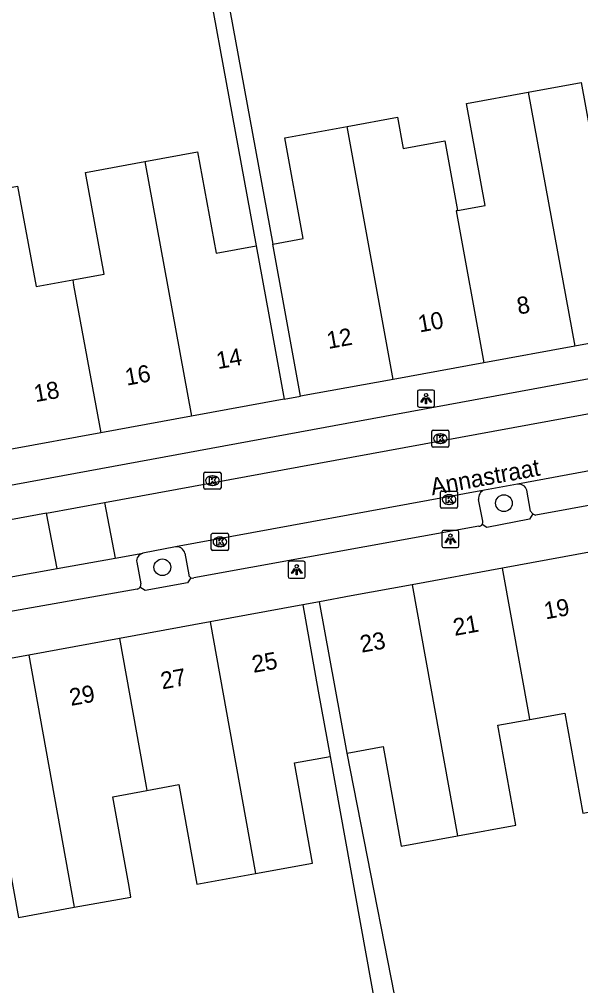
# Model space of a CAD drawing. Extents: x 159718 to 160783, y 383290 to 384030.
# Drawn here: x 160263.5 to 160296.4, y 383643.1 to 383699.6 of the extents above; entities that cross this region are included whole.
import ezdxf

# ---------------------------------------------------------------- set-up
doc = ezdxf.new("R2010")
doc.units = 0
for name, color, linetype in [('IMGEO_Boom', 7, 'Continuous'), ('IMGEO_Kolk', 7, 'Continuous'), ('IMGEO_Lichtpunt', 7, 'Continuous'), ('IMGEO_Openbare_ruimte_label', 7, 'Continuous'), ('IMGEO_Pand', 7, 'Continuous'), ('IMGEO_Pand_nummerreeks', 7, 'Continuous'), ('IMGEO_Parkeervlak_open', 7, 'Continuous'), ('IMGEO_Rijbaan_lokaal_open', 7, 'Continuous'), ('IMGEO_Voetpad_open', 7, 'Continuous')]:
    doc.layers.add(name, color=color, linetype=linetype)

msp = doc.modelspace()

# ---------------------------------------------------------------- linework, layer by layer
at = {"layer": 'IMGEO_Boom'}
for centre in [(160291.886, 383671.268), (160271.907, 383667.52)]:
    msp.add_circle(centre, 0.489, dxfattribs=at)
at = {"layer": 'IMGEO_Kolk'}
for p, q in [((160287.664, 383674.615), (160287.664, 383675.467)), ((160287.739, 383675.541), (160288.591, 383675.541)), ((160288.152, 383675.321), (160288.177, 383675.321)), ((160288.665, 383675.467), (160288.665, 383674.615)), ((160288.175, 383674.761), (160288.15, 383674.761)), ((160288.591, 383674.541), (160287.739, 383674.541)), ((160274.337, 383672.156), (160274.337, 383673.008)), ((160274.412, 383673.082), (160275.264, 383673.082)), ((160275.338, 383673.008), (160275.338, 383672.156)), ((160274.848, 383672.302), (160274.823, 383672.302)), ((160274.825, 383672.862), (160274.85, 383672.862)), ((160275.264, 383672.082), (160274.412, 383672.082)), ((160288.176, 383671.053), (160288.176, 383671.905)), ((160288.251, 383671.979), (160289.103, 383671.979)), ((160288.664, 383671.759), (160288.689, 383671.759)), ((160289.177, 383671.905), (160289.177, 383671.053)), ((160288.687, 383671.199), (160288.662, 383671.199)), ((160289.103, 383670.979), (160288.251, 383670.979)), ((160274.846, 383669.506), (160275.698, 383669.506)), ((160274.771, 383668.58), (160274.771, 383669.432)), ((160275.259, 383669.286), (160275.284, 383669.286)), ((160275.772, 383669.432), (160275.772, 383668.58)), ((160275.698, 383668.506), (160274.846, 383668.506)), ((160275.282, 383668.726), (160275.257, 383668.726))]:
    msp.add_line(p, q, dxfattribs=at)
for points in [[(160287.664, 383674.615), (160287.664, 383675.467)], [(160287.739, 383675.541), (160288.591, 383675.541)], [(160287.985, 383675.241), (160288.108, 383675.241), (160288.108, 383675.09), (160288.238, 383675.241), (160288.402, 383675.241), (160288.256, 383675.09), (160288.409, 383674.841), (160288.257, 383674.841), (160288.172, 383675.005), (160288.108, 383674.938), (160288.108, 383674.841), (160287.985, 383674.841), (160287.985, 383675.241)], [(160288.665, 383675.467), (160288.665, 383674.615)], [(160288.591, 383674.541), (160287.739, 383674.541)], [(160274.337, 383672.156), (160274.337, 383673.008)], [(160274.412, 383673.082), (160275.264, 383673.082)], [(160275.338, 383673.008), (160275.338, 383672.156)], [(160274.658, 383672.782), (160274.781, 383672.782), (160274.781, 383672.631), (160274.911, 383672.782), (160275.075, 383672.782), (160274.929, 383672.631), (160275.082, 383672.382), (160274.93, 383672.382), (160274.845, 383672.546), (160274.781, 383672.479), (160274.781, 383672.382), (160274.658, 383672.382), (160274.658, 383672.782)], [(160275.264, 383672.082), (160274.412, 383672.082)], [(160288.176, 383671.053), (160288.176, 383671.905)], [(160288.251, 383671.979), (160289.103, 383671.979)], [(160289.177, 383671.905), (160289.177, 383671.053)], [(160288.497, 383671.679), (160288.62, 383671.679), (160288.62, 383671.528), (160288.75, 383671.679), (160288.914, 383671.679), (160288.768, 383671.528), (160288.921, 383671.279), (160288.769, 383671.279), (160288.684, 383671.443), (160288.62, 383671.376), (160288.62, 383671.279), (160288.497, 383671.279), (160288.497, 383671.679)], [(160289.103, 383670.979), (160288.251, 383670.979)], [(160274.846, 383669.506), (160275.698, 383669.506)], [(160274.771, 383668.58), (160274.771, 383669.432)], [(160275.092, 383669.206), (160275.215, 383669.206), (160275.215, 383669.055), (160275.345, 383669.206), (160275.509, 383669.206), (160275.363, 383669.055), (160275.516, 383668.806), (160275.364, 383668.806), (160275.279, 383668.97), (160275.215, 383668.903), (160275.215, 383668.806), (160275.092, 383668.806), (160275.092, 383669.206)], [(160275.772, 383669.432), (160275.772, 383668.58)], [(160275.698, 383668.506), (160274.846, 383668.506)]]:
    msp.add_lwpolyline(points, dxfattribs=at)
for centre, start, end in [((160287.741, 383675.465), 91.552, 178.448), ((160287.741, 383675.465), 91.552, 178.448), ((160288.589, 383675.465), 1.552, 88.448), ((160288.589, 383675.465), 1.552, 88.448), ((160287.741, 383674.617), 181.552, 268.448), ((160287.741, 383674.617), 181.552, 268.448), ((160288.589, 383674.617), 271.552, 358.448), ((160288.589, 383674.617), 271.552, 358.448), ((160274.414, 383673.006), 91.552, 178.448), ((160274.414, 383673.006), 91.552, 178.448), ((160275.262, 383673.006), 1.552, 88.448), ((160275.262, 383673.006), 1.552, 88.448), ((160274.414, 383672.158), 181.552, 268.448), ((160274.414, 383672.158), 181.552, 268.448), ((160275.262, 383672.158), 271.552, 358.448), ((160275.262, 383672.158), 271.552, 358.448), ((160288.253, 383671.903), 91.552, 178.448), ((160288.253, 383671.903), 91.552, 178.448), ((160289.101, 383671.903), 1.552, 88.448), ((160289.101, 383671.903), 1.552, 88.448), ((160288.253, 383671.055), 181.552, 268.448), ((160288.253, 383671.055), 181.552, 268.448), ((160289.101, 383671.055), 271.552, 358.448), ((160289.101, 383671.055), 271.552, 358.448), ((160274.848, 383669.43), 91.552, 178.448), ((160274.848, 383669.43), 91.552, 178.448), ((160275.696, 383669.43), 1.552, 88.448), ((160275.696, 383669.43), 1.552, 88.448), ((160274.848, 383668.582), 181.552, 268.448), ((160274.848, 383668.582), 181.552, 268.448), ((160275.696, 383668.582), 271.552, 358.448), ((160275.696, 383668.582), 271.552, 358.448)]:
    msp.add_arc(centre, 0.0765, start, end, dxfattribs=at)
for centre, major_axis, ratio, start_param, end_param in [((160288.151, 383675.041), (-0.387, 0.002), 0.722429, 4.712389, 7.853982), ((160288.176, 383675.041), (-0.39, 0.002), 0.717154, 1.570796, 4.712389), ((160274.824, 383672.582), (-0.387, 0.002), 0.722429, 4.712389, 7.853982), ((160274.849, 383672.582), (-0.39, 0.002), 0.717154, 1.570796, 4.712389), ((160288.663, 383671.479), (-0.387, 0.002), 0.722429, 4.712389, 7.853982), ((160288.688, 383671.479), (-0.39, 0.002), 0.717154, 1.570796, 4.712389), ((160275.258, 383669.006), (-0.387, 0.002), 0.722429, 4.712389, 7.853982), ((160275.283, 383669.006), (-0.39, 0.002), 0.717154, 1.570796, 4.712389)]:
    msp.add_ellipse(centre, major_axis=major_axis, ratio=ratio, start_param=start_param, end_param=end_param, dxfattribs=at)
at = {"layer": 'IMGEO_Lichtpunt'}
for p, q in [((160286.831, 383677.789), (160286.831, 383676.982)), ((160286.831, 383677.789), (160286.831, 383676.982)), ((160287.733, 383677.884), (160286.925, 383677.884)), ((160287.733, 383677.884), (160286.925, 383677.884)), ((160287.827, 383676.982), (160287.827, 383677.789)), ((160287.827, 383676.982), (160287.827, 383677.789)), ((160286.925, 383676.888), (160287.733, 383676.888)), ((160286.925, 383676.888), (160287.733, 383676.888)), ((160288.257, 383669.575), (160288.257, 383668.768)), ((160288.257, 383669.575), (160288.257, 383668.768)), ((160289.159, 383669.67), (160288.351, 383669.67)), ((160289.159, 383669.67), (160288.351, 383669.67)), ((160289.253, 383668.768), (160289.253, 383669.575)), ((160289.253, 383668.768), (160289.253, 383669.575)), ((160288.351, 383668.674), (160289.159, 383668.674)), ((160288.351, 383668.674), (160289.159, 383668.674)), ((160280.169, 383667.873), (160279.361, 383667.873)), ((160280.169, 383667.873), (160279.361, 383667.873)), ((160279.267, 383667.778), (160279.267, 383666.971)), ((160279.267, 383667.778), (160279.267, 383666.971)), ((160280.263, 383666.971), (160280.263, 383667.778)), ((160280.263, 383666.971), (160280.263, 383667.778)), ((160279.361, 383666.877), (160280.169, 383666.877)), ((160279.361, 383666.877), (160280.169, 383666.877))]:
    msp.add_line(p, q, dxfattribs=at)
for points in [[(160287.205, 383677.453), (160287.244, 383677.425), (160287.056, 383677.163), (160287.018, 383677.19), (160287.205, 383677.453)], [(160287.307, 383677.405), (160287.354, 383677.405), (160287.354, 383677.083), (160287.307, 383677.083), (160287.307, 383677.405)], [(160287.417, 383677.425), (160287.455, 383677.452), (160287.642, 383677.19), (160287.603, 383677.162), (160287.417, 383677.425)], [(160288.631, 383669.239), (160288.67, 383669.211), (160288.482, 383668.949), (160288.444, 383668.976), (160288.631, 383669.239)], [(160288.733, 383669.191), (160288.78, 383669.191), (160288.78, 383668.869), (160288.733, 383668.869), (160288.733, 383669.191)], [(160288.843, 383669.211), (160288.881, 383669.238), (160289.068, 383668.976), (160289.029, 383668.948), (160288.843, 383669.211)], [(160279.641, 383667.442), (160279.68, 383667.414), (160279.492, 383667.152), (160279.454, 383667.179), (160279.641, 383667.442)], [(160279.743, 383667.394), (160279.79, 383667.394), (160279.79, 383667.072), (160279.743, 383667.072), (160279.743, 383667.394)], [(160279.853, 383667.414), (160279.891, 383667.441), (160280.078, 383667.179), (160280.039, 383667.151), (160279.853, 383667.414)]]:
    msp.add_lwpolyline(points, dxfattribs=at)
for centre in [(160287.33, 383677.587), (160288.756, 383669.373), (160279.766, 383667.576)]:
    msp.add_circle(centre, 0.0994, dxfattribs=at)
for centre, start, end in [((160286.925, 383677.789), 90, 180), ((160286.925, 383677.789), 90, 180), ((160287.733, 383677.789), 0, 90), ((160287.733, 383677.789), 0, 90), ((160286.925, 383676.982), 180, 270), ((160286.925, 383676.982), 180, 270), ((160287.733, 383676.982), 270, 0), ((160287.733, 383676.982), 270, 360), ((160288.351, 383669.575), 90, 180), ((160288.351, 383669.575), 90, 180), ((160289.159, 383669.575), 0, 90), ((160289.159, 383669.575), 0, 90), ((160288.351, 383668.768), 180, 270), ((160288.351, 383668.768), 180, 270), ((160289.159, 383668.768), 270, 0), ((160289.159, 383668.768), 270, 360), ((160279.361, 383667.778), 90, 180), ((160279.361, 383667.778), 90, 180), ((160280.169, 383667.778), 0, 90), ((160280.169, 383667.778), 0, 90), ((160279.361, 383666.971), 180, 270), ((160279.361, 383666.971), 180, 270), ((160280.169, 383666.971), 270, 0), ((160280.169, 383666.971), 270, 360)]:
    msp.add_arc(centre, 0.0946, start, end, dxfattribs=at)
at = {"layer": 'IMGEO_Pand'}
for points in [[(160293.306, 383695.296), (160296.401, 383695.862), (160297.492, 383689.904), (160299.702, 383690.309)], [(160289.166, 383688.38), (160290.787, 383688.677), (160289.696, 383694.635), (160293.306, 383695.296)], [(160293.306, 383695.296), (160296.023, 383680.451)], [(160282.707, 383693.297), (160285.651, 383693.835), (160285.986, 383692.007), (160288.42, 383692.453), (160289.166, 383688.38)], [(160278.362, 383686.412), (160280.151, 383686.74), (160279.072, 383692.631), (160282.707, 383693.297)], [(160285.413, 383678.507), (160282.707, 383693.297)], [(160270.881, 383691.239), (160273.968, 383691.806), (160275.054, 383685.888), (160277.395, 383686.319)], [(160266.664, 383684.32), (160268.504, 383684.658), (160267.413, 383690.603), (160270.881, 383691.239)], [(160270.881, 383691.239), (160273.613, 383676.352)], [(160260.277, 383689.218), (160263.443, 383689.798), (160264.519, 383683.927), (160266.664, 383684.32)], [(160289.166, 383688.38), (160289.091, 383688.366), (160290.718, 383679.478)], [(160277.395, 383686.319), (160278.137, 383682.274), (160279.04, 383677.348)], [(160279.991, 383677.515), (160279.088, 383682.449), (160278.362, 383686.412)], [(160266.664, 383684.32), (160266.719, 383684.014), (160268.304, 383675.379)], [(160301.328, 383681.422), (160296.023, 383680.451)], [(160296.023, 383680.451), (160290.718, 383679.478)], [(160290.718, 383679.478), (160285.413, 383678.507)], [(160285.413, 383678.507), (160279.991, 383677.515)], [(160279.04, 383677.348), (160273.613, 383676.352)], [(160273.613, 383676.352), (160268.304, 383675.379)], [(160268.304, 383675.379), (160262.995, 383674.406)], [(160297.104, 383668.443), (160291.809, 383667.47)], [(160291.809, 383667.47), (160286.516, 383666.498)], [(160293.409, 383658.625), (160293.385, 383658.76), (160291.809, 383667.47)], [(160286.516, 383666.498), (160282.946, 383665.841), (160281.106, 383665.503)], [(160286.516, 383666.498), (160289.172, 383651.814)], [(160280.13, 383665.327), (160274.696, 383664.332)], [(160280.13, 383665.327), (160281.028, 383660.281), (160281.718, 383656.465)], [(160282.707, 383656.648), (160282.011, 383660.493), (160281.106, 383665.503)], [(160274.696, 383664.332), (160269.392, 383663.361)], [(160274.696, 383664.332), (160277.36, 383649.607)], [(160269.392, 383663.361), (160264.089, 383662.39)], [(160269.392, 383663.361), (160270.958, 383654.701), (160271, 383654.467)], [(160264.089, 383662.39), (160258.785, 383661.419)], [(160264.089, 383662.39), (160266.757, 383647.64)], [(160293.409, 383658.625), (160295.443, 383658.993), (160296.501, 383653.145), (160299.764, 383653.735)], [(160289.172, 383651.814), (160292.59, 383652.432), (160291.531, 383658.286), (160293.409, 383658.625)], [(160282.707, 383656.648), (160284.826, 383657.032), (160285.878, 383651.218), (160289.172, 383651.814)], [(160277.36, 383649.607), (160280.691, 383650.21), (160279.627, 383656.087), (160281.718, 383656.465)], [(160271, 383654.467), (160272.877, 383654.823), (160273.932, 383648.987), (160277.36, 383649.607)], [(160266.757, 383647.64), (160270.071, 383648.239), (160269.961, 383648.85), (160269.017, 383654.091), (160271, 383654.467)], [(160260.398, 383652.502), (160262.443, 383652.872), (160263.497, 383647.05), (160266.757, 383647.64)]]:
    msp.add_lwpolyline(points, dxfattribs=at)
at = {"layer": 'IMGEO_Parkeervlak_open'}
for points in [[(160293.442, 383670.791), (160293.227, 383672.025)], [(160290.658, 383670.224), (160290.398, 383671.491)], [(160270.407, 383667.814), (160270.653, 383666.553)], [(160273.226, 383668.337), (160273.451, 383667.084)]]:
    msp.add_lwpolyline(points, dxfattribs=at)
for centre, radius, start, end in [((160292.745, 383671.886), 0.502, 16.1226, 98.5631), ((160290.908, 383671.55), 0.514, 109.2509, 186.5869), ((160293.843, 383671.028), 0.465, 210.5631, 233.82), ((160290.381, 383670.194), 0.278, 323.4889, 6.2484), ((160272.739, 383668.225), 0.499, 12.9215, 97.8601), ((160270.883, 383667.876), 0.48, 104.6245, 187.4452), ((160273.659, 383667.095), 0.208, 182.9783, 246.5773), ((160270.343, 383666.535), 0.311, 325.5496, 3.3412)]:
    msp.add_arc(centre, radius, start, end, dxfattribs=at)
at = {"layer": 'IMGEO_Rijbaan_lokaal_open'}
for points in [[(160268.529, 383671.299), (160312.074, 383679.307), (160320.087, 383681.393)], [(160310.761, 383675.724), (160292.67, 383672.382)], [(160292.67, 383672.382), (160290.739, 383672.035)], [(160290.739, 383672.035), (160272.671, 383668.72)], [(160265.139, 383670.682), (160268.529, 383671.299)], [(160268.529, 383671.299), (160269.14, 383668.049)], [(160265.139, 383670.682), (160243.406, 383666.677)], [(160265.758, 383667.44), (160265.139, 383670.682)], [(160272.671, 383668.72), (160270.762, 383668.341)], [(160265.758, 383667.44), (160269.14, 383668.049)], [(160269.14, 383668.049), (160270.762, 383668.341)], [(160252.683, 383665.088), (160265.758, 383667.44)]]:
    msp.add_lwpolyline(points, dxfattribs=at)
at = {"layer": 'IMGEO_Voetpad_open'}
for points in [[(160270.378, 383710.469), (160271.773, 383710.707), (160272.973, 383710.425), (160277.395, 383686.319)], [(160274.041, 383710.174), (160274.004, 383710.183), (160278.362, 383686.412)], [(160243.738, 383668.782), (160311.679, 383681.281), (160321.168, 383683.787), (160342.669, 383689.488)], [(160279.04, 383677.348), (160279.991, 383677.515)], [(160310.394, 383673.609), (160293.746, 383670.571)], [(160293.568, 383670.652), (160293.381, 383670.327), (160290.879, 383669.845), (160290.605, 383670.028)], [(160290.415, 383669.915), (160273.74, 383666.903)], [(160273.576, 383666.904), (160273.38, 383666.614), (160270.895, 383666.166), (160270.599, 383666.359)], [(160270.429, 383666.237), (160253.75, 383663.297)], [(160281.106, 383665.503), (160280.13, 383665.327)], [(160286.47, 383637.469), (160282.707, 383656.648)], [(160281.718, 383656.465), (160285.268, 383636.828), (160285.786, 383634.846), (160285.674, 383634.817)]]:
    msp.add_lwpolyline(points, dxfattribs=at)
for centre, radius, start, end in [((160293.847, 383671.029), 0.469, 233.5012, 257.5624), ((160290.379, 383670.191), 0.278, 277.3374, 324.1456), ((160273.659, 383667.099), 0.212, 246.8972, 292.4041), ((160270.348, 383666.53), 0.304, 285.5033, 325.8267)]:
    msp.add_arc(centre, radius, start, end, dxfattribs=at)

# ---------------------------------------------------------------- texts
at = {"layer": 'IMGEO_Openbare_ruimte_label'}
msp.add_text('Annastraat', height=1, rotation=10.433, dxfattribs=at).set_placement((160287.686, 383671.723))
at = {"layer": 'IMGEO_Pand_nummerreeks'}
for s, rotation, p in [('8', 10.2502, (160292.737, 383682.292)), ('10', 10.2502, (160286.953, 383681.246)), ('12', 10.2502, (160281.617, 383680.281)), ('14', 10.2559, (160275.159, 383679.101)), ('16', 10.2559, (160269.822, 383678.136)), ('18', 10.2559, (160264.488, 383677.171)), ('19', 10.2559, (160294.32, 383664.468)), ('21', 10.2559, (160289.006, 383663.506)), ('23', 10.2559, (160283.559, 383662.521)), ('25', 10.2559, (160277.239, 383661.343)), ('27', 10.2559, (160271.9, 383660.377)), ('29', 10.2559, (160266.561, 383659.411))]:
    msp.add_text(s, height=1, rotation=rotation, dxfattribs=at).set_placement(p)

doc.saveas('drawing.dxf')
